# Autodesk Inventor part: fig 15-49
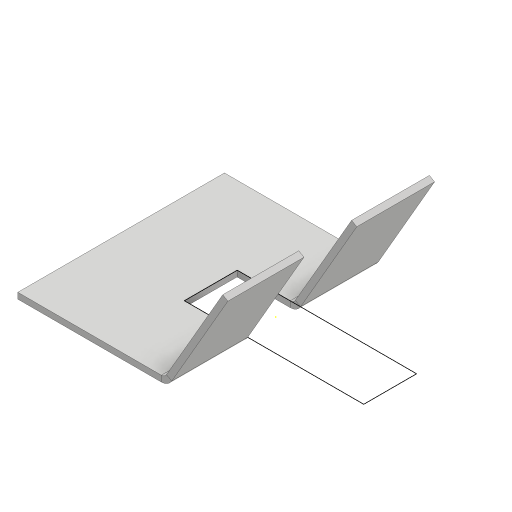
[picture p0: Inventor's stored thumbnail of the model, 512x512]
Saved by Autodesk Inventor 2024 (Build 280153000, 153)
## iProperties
Created: 2015-07
Part Number: fig 15-49
Material: Generic
Document SubType Name: Sheet Metal
Designer: Sandeep
Density: 1 g/cm^3
Sheet Metal Rule: Default_mm
Appearance: Default
Author: Sandeep
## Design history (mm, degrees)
node "Face1"
  sketch "Sketch1"
    geometry: L1 (-12.609, 8.313)-(0, 8.313); L2 (0, 8.313)-(0, -9.006); L3 (0, -9.006)-(-12.609, -9.006); L4 (-12.609, -9.006)-(-12.609, 8.313); 1 further point
    constraints: 8 end point, 2 parallel, 1 horizontal, 1 perpendicular
node "Flange1"
sketch "Sketch3"
  geometry: L1 (9.998, 1.795)-(-5.034, 1.795); L2 (-5.034, 1.795)-(-5.034, -2.633); L3 (-5.034, -2.633)-(9.998, -2.633); L4 (9.998, -2.633)-(9.998, 1.795); 1 further point
  constraints: 8 end point, 2 parallel, 1 horizontal, 1 perpendicular
cut "Cut1" sketch "Sketch3" dims "d11" = 0.5 (= Thickness), "d12" = 0
body "Solid1"
face "Plate1" dims "d13" = 0.5 (= Thickness)
sketch "Sketch2"
  geometry: L1 (0, 10)-(-17.319, 10); L2 (-17.319, 10)-(-17.319, 0); 1 other entity
  constraints: 4 end point, 4 other
face "Plate2" dims "d1" = 0.5 (= BendReliefWidth), "d2" = 0.25 (= BendReliefDepth), "d3" = 1 (= MinimumRemnant), "d4" = 0.5 (= BendRadius), "d5" = 10, "d6" = 60 deg, "d7" = 0.5 (= BendRadius), "d8" = 2 (= CornerReliefSize), "d9" = 0.5 (= GapSize), "d10" = 0.5 (= JacobiRadiusSize), "d13" = 0.5 (= Thickness), "SeamGap" = 0.01
bend "Bend1" dims "d1" = 0.5 (= BendReliefWidth), "d2" = 0.25 (= BendReliefDepth), "d3" = 1 (= MinimumRemnant), "d4" = 0.5 (= BendRadius), "d5" = 10, "d6" = 60 deg, "d7" = 0.5 (= BendRadius), "d13" = 0.5 (= Thickness), "SeamGap" = 0.01
feature "Corner1" dims "d5" = 10, "d6" = 60 deg, "d8" = 2 (= CornerReliefSize), "d9" = 0.5 (= GapSize), "d10" = 0.5 (= JacobiRadiusSize)
other parameters: "Thickness" = 0.5, "BendRadius" = 0.5 (= Thickness), "BendReliefWidth" = 0.5 (= Thickness), "BendReliefDepth" = 0.25 (= 0.5 x Thickness), "CornerReliefSize" = 2 (= 4 x Thickness), "MinimumRemnant" = 1 (= 2 x Thickness), "TransitionRadius" = 0.5 (= BendRadius), "JacobiRadiusSize" = 0.5 (= BendRadius), "GapSize" = 0.5 (= Thickness), "d0" = 0.5 (= BendRadius)
